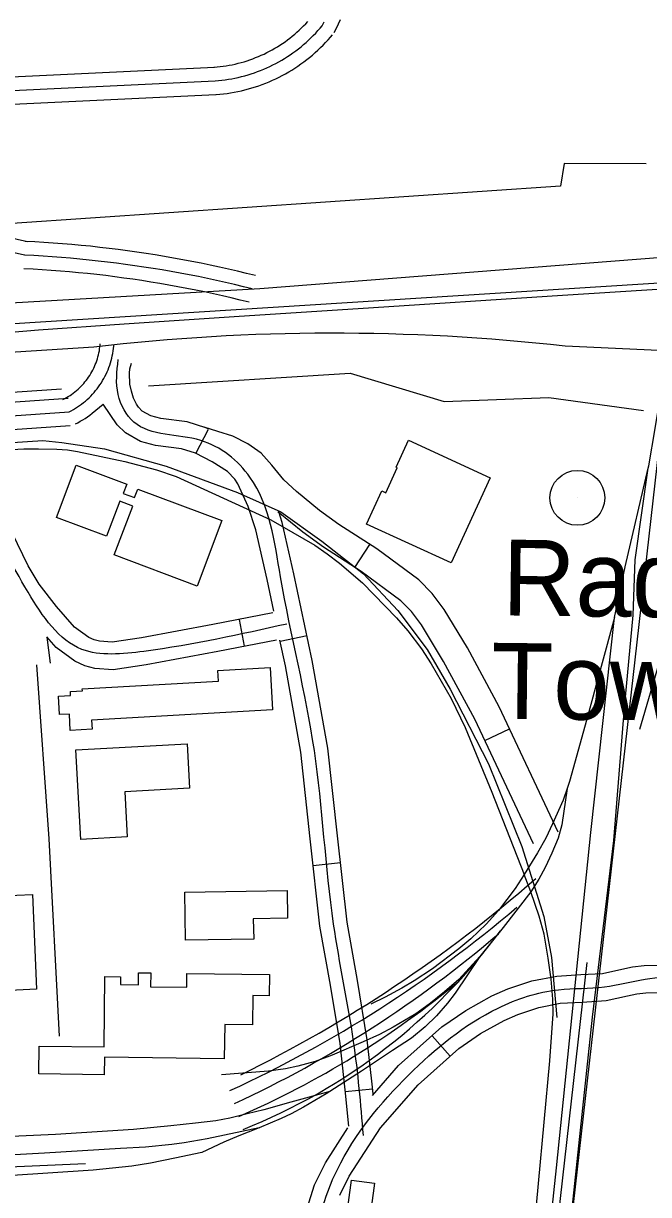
# Model space of a CAD drawing. Extents: x 3313442 to 3351311, y 721974 to 747360.
# Drawn here: x 3327167 to 3327852, y 729153 to 730435 of the extents above; entities that cross this region are included whole.
import ezdxf

# ---------------------------------------------------------------- set-up
doc = ezdxf.new("R2010")
doc.units = 0
for name, color, linetype in [('V-BLDG-OTLN', 7, 'Continuous'), ('V-RAIL-TRAK', 7, 'Continuous'), ('V-ROAD-CNTR', 7, 'Continuous'), ('V-TOPO-SHOR', 7, 'Continuous'), ('V-TOPO-TOWR', 7, 'Continuous'), ('V-TOPO-TOWR-IDEN', 7, 'Continuous')]:
    doc.layers.add(name, color=color, linetype=linetype)

msp = doc.modelspace()

# ---------------------------------------------------------------- linework, layer by layer
at = {"layer": 'V-BLDG-OTLN'}
for points in [[(3327588.8, 729979), (3327678.2, 729937.9), (3327635.5, 729844.9), (3327543, 729887.3), (3327559.6, 729923.5), (3327563.9, 729921.5), (3327576.5, 729948.9), (3327575.3, 729949.4)], [(3327203.4, 729894.6), (3327224.9, 729951.8), (3327280.4, 729930.9), (3327276.6, 729920.9), (3327289, 729916.2), (3327292.5, 729925.6), (3327384.5, 729891), (3327357.6, 729819.3), (3327266.7, 729853.5), (3327286.9, 729907), (3327272.7, 729912.4), (3327258.2, 729873.9)], [(3327241.9, 729672.7), (3327242.5, 729662.7), (3327218.6, 729661.4), (3327217.6, 729679.2), (3327206.7, 729678.6), (3327205.6, 729698.7), (3327219, 729699.5), (3327218.8, 729703.8), (3327231.8, 729704.5), (3327231.6, 729706.9), (3327380.8, 729715.3), (3327380.1, 729727), (3327437.4, 729730.3), (3327440, 729683.9)], [(3327230.1, 729542), (3327224.8, 729640.1), (3327346.7, 729646.7), (3327349.3, 729598), (3327278.3, 729594.1), (3327281, 729544.8)], [(3327344.1, 729484.3), (3327455.9, 729485.9), (3327456.4, 729455.6), (3327419, 729455.1), (3327419.4, 729432.8), (3327344.9, 729431.7)], [(3327177.1, 729481.7), (3327181.7, 729377.9), (3327130, 729375.6), (3327125.4, 729479.4)], [(3327255.6, 729314.7), (3327256.6, 729391.7), (3327273.7, 729391.5), (3327273.6, 729383.1), (3327293.1, 729382.8), (3327293.2, 729395.9), (3327306.8, 729395.7), (3327306.6, 729380.7), (3327346.1, 729380.1), (3327346.3, 729395.2), (3327436.6, 729394), (3327436.3, 729370.7), (3327418.6, 729371), (3327418.1, 729339), (3327387.7, 729339.4), (3327387.2, 729301.7), (3327255.9, 729303.5), (3327255.6, 729284.1), (3327184.2, 729285.1), (3327184.6, 729315.7)], [(3327514.8, 729081.9), (3327526.5, 729168.8), (3327551.6, 729165.4), (3327539.9, 729078.5)]]:
    msp.add_lwpolyline(points, close=True, dxfattribs=at)
at = {"layer": 'V-RAIL-TRAK'}
for points in [[(3327851.4, 729948.5), (3327852, 729951), (3327858.9, 729992), (3327884.5, 730146.1), (3327904.5, 730266.7), (3327916, 730340.5), (3327930.1, 730430.7), (3327952.4, 730568.9)], [(3327183.8, 730099.8), (3327277.7, 730106.6), (3327403.5, 730115), (3327533.8, 730123.3), (3327757.4, 730137.9), (3327884.5, 730146.1), (3327892.7, 730146.7), (3328018.3, 730155.8), (3328042.5, 730157.3), (3328057.1, 730158.3), (3328070.7, 730159.1), (3328086.4, 730159.6), (3328145.1, 730159.2), (3328193.8, 730158.7), (3328212.7, 730158.5), (3328228.8, 730157.8), (3328260.8, 730155.5), (3328288.9, 730153.2), (3328318.8, 730150), (3328375.5, 730142.9), (3328414.4, 730137.2), (3328463.7, 730128.5), (3328497.9, 730121.4)], [(3327014.9, 730087.4), (3327110.7, 730093.9), (3327183.8, 730099.8)], [(3327059.4, 729961.3), (3327127.5, 729967.6), (3327167.7, 729969.8), (3327183.7, 729969.7), (3327203.9, 729969.4)], [(3327203.9, 729969.4), (3327215.5, 729968.4), (3327226.4, 729966.7), (3327278.5, 729955.7), (3327313, 729946.7), (3327334.4, 729939.5), (3327438, 729892), (3327486.2, 729864), (3327499.8, 729854.8), (3327513.5, 729844.6), (3327538.4, 729822.8), (3327575.6, 729784.7), (3327588.1, 729770.4), (3327603.2, 729750.5), (3327613.7, 729734.4), (3327635.5, 729696.4), (3327650.9, 729664.5), (3327680.2, 729593.8), (3327715.7, 729503.6)], [(3327658.3, 728335.8), (3327679.9, 728538.1), (3327686.9, 728603.1), (3327698.6, 728695.6), (3327703.3, 728743.6), (3327716.3, 728857.1), (3327751, 729182.2), (3327788.4, 729549.5), (3327814.6, 729784.9), (3327826.2, 729840.6), (3327851.4, 729948.5)], [(3327725.1, 728725.6), (3327734.4, 728833.8), (3327748.4, 728955.9), (3327762.4, 729082.6), (3327790.5, 729347.4), (3327813.8, 729540.9), (3327825.5, 729686), (3327834.9, 729787.4), (3327837, 729848), (3327851.4, 729948.5)], [(3327814.6, 729784.9), (3327784, 729673.7), (3327765.3, 729605.5), (3327762.6, 729597.6)], [(3327762.6, 729597.6), (3327756.8, 729557.8), (3327752.8, 729543.2), (3327746, 729526.9), (3327738.6, 729511.2), (3327731.6, 729498.5), (3327722.7, 729484.5), (3327692.7, 729445.6), (3327667.1, 729413.7), (3327643.9, 729388.4), (3327628.3, 729375), (3327613.1, 729362.7), (3327597, 729351.1), (3327572, 729336.2), (3327557.3, 729328.5), (3327539.4, 729320.3), (3327505.4, 729305.7), (3327486.6, 729298.7), (3327467.7, 729293.6), (3327454.1, 729290.6), (3327435.7, 729288.3), (3327384, 729284.2)], [(3327762.6, 729597.6), (3327758.3, 729584.8), (3327746.7, 729558.9), (3327739.3, 729543.5), (3327730.1, 729527.2), (3327715.7, 729503.6), (3327705.6, 729488.1), (3327687.6, 729464.2), (3327674, 729449), (3327657.3, 729433.1), (3327643.9, 729422)], [(3327703.3, 728743.6), (3327706.3, 728858.9), (3327706.8, 728889.1), (3327707.5, 728915.7), (3327709.3, 728943.5), (3327714.9, 729003.8), (3327725.1, 729097.9), (3327743.5, 729299.5), (3327747.2, 729350.8), (3327747, 729367.2), (3327745.1, 729388.9), (3327741.9, 729411.8), (3327737.4, 729438.2), (3327731.8, 729458), (3327722.7, 729484.5), (3327715.7, 729503.6)], [(3327643.9, 729422), (3327615, 729400.4), (3327595.2, 729387.1), (3327581.7, 729379), (3327563.3, 729369.3), (3327547.5, 729361.6)], [(3327667.1, 729413.7), (3327640, 729373.5), (3327631.5, 729362.8), (3327619.7, 729348.9), (3327607.2, 729336.9), (3327592.3, 729324.5), (3327571.3, 729310.9), (3327537.4, 729288.2), (3327502.6, 729265.8)], [(3327502.6, 729265.8), (3327460, 729254.1), (3327430.5, 729245.8), (3327412.4, 729241.3), (3327393.3, 729236.8), (3327377.8, 729233.7), (3327355.7, 729231.2), (3327328.6, 729228.2), (3327287.8, 729224.5), (3327202.4, 729218.8), (3327121.8, 729215.3), (3326843.8, 729200.9), (3326713, 729190.5), (3326658.4, 729186.5), (3326461.7, 729173.4), (3326168.2, 729152.8), (3326073.1, 729146.5)], [(3327502.6, 729265.8), (3327498.6, 729263.2), (3327473.9, 729248.8), (3327460.3, 729241.5), (3327449.5, 729236.4), (3327425.4, 729226.2), (3327423.7, 729225.5), (3327403, 729217.4), (3327386.6, 729210.5), (3327362.5, 729199.2), (3327333, 729192.8), (3327306.6, 729187.4), (3327286.1, 729184.2), (3327243.5, 729179.7), (3327011.5, 729164.4), (3326950.7, 729160.3), (3326888.4, 729156.2)], [(3327426, 729226.3), (3327425.4, 729226.2), (3327368.4, 729214.1), (3327343.2, 729209.7), (3327329.7, 729208), (3327300.9, 729205.1), (3327273.4, 729203.4), (3327190.4, 729198.3), (3327104.8, 729193.6), (3326981.7, 729185.9), (3326856.7, 729179.1), (3326685.3, 729167.5), (3326571.1, 729159.8)]]:
    msp.add_lwpolyline(points, dxfattribs=at)
at = {"layer": 'V-ROAD-CNTR'}
for p, q in [((3327356.1, 729964.6), (3327369.8, 729991.3)), ((3327530.2, 729839.8), (3327546.4, 729865)), ((3327409.4, 729753.5), (3327403.7, 729782.9)), ((3327448.5, 729759), (3327477.8, 729765.2)), ((3327672.5, 729650.2), (3327699.6, 729663)), ((3327484.6, 729513.3), (3327514.5, 729516.6)), ((3327614.8, 729327), (3327634.7, 729304.6)), ((3327519.7, 729266.1), (3327549.6, 729269))]:
    msp.add_line(p, q, dxfattribs=at)
for points in [[(3327375.9, 730387.5), (3327379.4, 730387.8), (3327382.7, 730388.2), (3327386, 730388.6), (3327389.3, 730389.1), (3327392.6, 730389.7), (3327395.9, 730390.3), (3327399.2, 730391), (3327402.4, 730391.8), (3327405.6, 730392.7), (3327408.9, 730393.6), (3327412.1, 730394.6), (3327415.2, 730395.6), (3327418.4, 730396.8), (3327421.5, 730398), (3327424.6, 730399.3), (3327427.6, 730400.6), (3327430.7, 730402), (3327433.7, 730403.5), (3327436.7, 730405), (3327439.6, 730406.6), (3327442.5, 730408.3), (3327445.4, 730410), (3327448.2, 730411.8), (3327451, 730413.6), (3327453.7, 730415.5), (3327456.4, 730417.5), (3327459.1, 730419.5), (3327461.7, 730421.6), (3327464.3, 730423.7), (3327466.8, 730425.9), (3327469.3, 730428.2), (3327471.7, 730430.5), (3327474, 730432.8), (3327476.4, 730435.2), (3327478.6, 730437.7)], [(3327377.1, 730372.6), (3327380.8, 730372.9), (3327384.5, 730373.3), (3327388.1, 730373.7), (3327391.7, 730374.3), (3327395.3, 730374.9), (3327398.9, 730375.6), (3327402.5, 730376.4), (3327406.1, 730377.3), (3327409.6, 730378.2), (3327413.2, 730379.2), (3327416.7, 730380.3), (3327420.2, 730381.5), (3327423.6, 730382.7), (3327427, 730384), (3327430.4, 730385.4), (3327433.8, 730386.9), (3327437.1, 730388.4), (3327440.4, 730390.1), (3327443.7, 730391.7), (3327446.9, 730393.5), (3327450.1, 730395.3), (3327453.2, 730397.2), (3327456.3, 730399.2), (3327459.4, 730401.2), (3327462.4, 730403.3), (3327465.4, 730405.5), (3327468.3, 730407.7), (3327471.2, 730410), (3327474, 730412.3), (3327476.8, 730414.7), (3327479.5, 730417.2), (3327482.1, 730419.7), (3327484.7, 730422.3), (3327487.3, 730424.9), (3327489.8, 730427.6), (3327492.2, 730430.4), (3327494.2, 730432.8)], [(3327494.2, 730432.8), (3327496.6, 730437.2)], [(3327507.4, 730425.7), (3327509.9, 730430.2), (3327512.3, 730434.9), (3327514.6, 730439.6)], [(3327378.4, 730357.6), (3327382.2, 730358), (3327386.2, 730358.4), (3327390.2, 730358.9), (3327394.1, 730359.5), (3327398.1, 730360.2), (3327402, 730360.9), (3327405.9, 730361.8), (3327409.8, 730362.7), (3327413.6, 730363.7), (3327417.5, 730364.9), (3327421.3, 730366), (3327425.1, 730367.3), (3327428.8, 730368.7), (3327432.6, 730370.1), (3327436.3, 730371.6), (3327439.9, 730373.2), (3327443.6, 730374.9), (3327447.2, 730376.7), (3327450.7, 730378.5), (3327454.2, 730380.4), (3327457.7, 730382.4), (3327461.1, 730384.4), (3327464.5, 730386.6), (3327467.8, 730388.8), (3327471.1, 730391.1), (3327474.3, 730393.4), (3327477.5, 730395.8), (3327480.6, 730398.3), (3327483.7, 730400.9), (3327486.7, 730403.5), (3327489.7, 730406.2), (3327492.6, 730409), (3327495.4, 730411.8), (3327498.2, 730414.7), (3327500.9, 730417.6), (3327503.5, 730420.6), (3327505.7, 730423.1)], [(3326610.2, 730351), (3327376.4, 730387.6)], [(3326595.9, 730335.3), (3327377.1, 730372.6)], [(3326611.6, 730321.1), (3327377.9, 730357.6)], [(3327171.8, 730196.4), (3327160.5, 730199), (3327149.2, 730201.6), (3327137.8, 730204), (3327126.4, 730206.4), (3327115, 730208.7), (3327103.6, 730210.9), (3327092.2, 730213), (3327080.7, 730215.1), (3327069.2, 730217.1), (3327057.8, 730218.9), (3327046.3, 730220.8), (3327034.8, 730222.5), (3327023.3, 730224.2), (3327011.7, 730225.7), (3327000.2, 730227.2), (3326988.6, 730228.6), (3326977.1, 730230), (3326965.5, 730231.2), (3326963.4, 730231.4)], [(3327168.5, 730181.8), (3327157.2, 730184.4), (3327146, 730186.9), (3327134.7, 730189.3), (3327123.4, 730191.7), (3327112.1, 730194), (3327100.8, 730196.2), (3327089.5, 730198.3), (3327078.1, 730200.3), (3327066.8, 730202.3), (3327055.4, 730204.1), (3327044, 730205.9), (3327032.6, 730207.7), (3327021.2, 730209.3), (3327009.8, 730210.9), (3326998.3, 730212.3), (3326986.9, 730213.7), (3326975.4, 730215.1), (3326964, 730216.3), (3326961.9, 730216.5)], [(3327421.5, 730159.3), (3327411.7, 730161.8), (3327401.7, 730164.2), (3327391.8, 730166.4), (3327381.8, 730168.7), (3327371.8, 730170.8), (3327361.8, 730172.9), (3327351.8, 730174.8), (3327341.8, 730176.7), (3327331.7, 730178.6), (3327321.6, 730180.3), (3327311.6, 730182), (3327301.5, 730183.5), (3327291.4, 730185), (3327281.2, 730186.5), (3327271.1, 730187.8), (3327261, 730189.1), (3327250.8, 730190.3), (3327240.7, 730191.4), (3327230.5, 730192.4), (3327220.4, 730193.3), (3327210.2, 730194.2), (3327200, 730194.9), (3327189.8, 730195.6), (3327179.6, 730196.3), (3327169.4, 730196.8), (3327169.2, 730196.8)], [(3321910.8, 729798.5), (3325213, 730008.8), (3325897.5, 730057.1), (3327426.3, 730145.3), (3327871.2, 730180)], [(3327417.9, 730144.8), (3327408.1, 730147.2), (3327398.3, 730149.5), (3327388.5, 730151.8), (3327378.6, 730154), (3327368.7, 730156.1), (3327358.8, 730158.2), (3327348.9, 730160.1), (3327339, 730162), (3327329.1, 730163.8), (3327319.1, 730165.5), (3327309.2, 730167.2), (3327299.2, 730168.7), (3327289.2, 730170.2), (3327279.2, 730171.6), (3327269.2, 730172.9), (3327259.2, 730174.2), (3327249.2, 730175.3), (3327239.1, 730176.4), (3327229.1, 730177.4), (3327219, 730178.4), (3327209, 730179.2), (3327198.9, 730180), (3327188.8, 730180.7), (3327178.8, 730181.3), (3327168.7, 730181.8), (3327168.5, 730181.8)], [(3328093, 730163.1), (3327927, 730155.1), (3326543.4, 730067.8), (3321912.7, 729768.7)], [(3327414.3, 730130.2), (3327404.6, 730132.6), (3327394.9, 730134.9), (3327385.1, 730137.2), (3327375.4, 730139.4), (3327365.7, 730141.4), (3327355.9, 730143.5), (3327346.1, 730145.4), (3327336.3, 730147.2), (3327326.5, 730149), (3327316.6, 730150.7), (3327306.8, 730152.3), (3327296.9, 730153.9), (3327287.1, 730155.4), (3327277.2, 730156.7), (3327267.3, 730158.1), (3327257.4, 730159.3), (3327247.5, 730160.4), (3327237.6, 730161.5), (3327227.6, 730162.5), (3327217.7, 730163.4), (3327207.8, 730164.3), (3327197.8, 730165), (3327187.9, 730165.7), (3327177.9, 730166.3), (3327167.9, 730166.8), (3327167.7, 730166.8)], [(3327600, 727590.2), (3327669.7, 728258.8), (3327867.9, 730009.3), (3327888, 730123.2)], [(3327244.3, 730081), (3325899.8, 729995.3), (3321914.9, 729742.6)], [(3327210.4, 730023.5), (3327212.6, 730024.6), (3327214.5, 730025.7), (3327216.4, 730026.9), (3327218.3, 730028.1), (3327220.1, 730029.3), (3327221.9, 730030.6), (3327223.7, 730032), (3327225.4, 730033.4), (3327227.1, 730034.9), (3327228.7, 730036.4), (3327230.3, 730037.9), (3327231.8, 730039.6), (3327233.3, 730041.2), (3327234.7, 730042.9), (3327236.1, 730044.6), (3327237.4, 730046.4), (3327238.7, 730048.2), (3327239.9, 730050.1), (3327241.1, 730052), (3327242.2, 730053.9), (3327243.2, 730055.9), (3327244.2, 730057.9), (3327245.2, 730059.9), (3327246, 730061.9), (3327246.8, 730064), (3327247.6, 730066.1), (3327248.3, 730068.2), (3327248.9, 730070.3), (3327249.4, 730072.5), (3327249.9, 730074.7), (3327250.4, 730076.8), (3327250.7, 730079), (3327251, 730081.2), (3327251.2, 730083.5), (3327251.3, 730084.6)], [(3327217.3, 730010.2), (3327219.7, 730011.4), (3327222, 730012.7), (3327224.3, 730014.1), (3327226.6, 730015.6), (3327228.8, 730017.1), (3327230.9, 730018.6), (3327233, 730020.3), (3327235.1, 730022), (3327237.1, 730023.7), (3327239.1, 730025.5), (3327241, 730027.4), (3327242.8, 730029.4), (3327244.6, 730031.3), (3327246.3, 730033.4), (3327248, 730035.5), (3327249.6, 730037.6), (3327251.1, 730039.8), (3327252.6, 730042), (3327254, 730044.3), (3327255.3, 730046.6), (3327256.6, 730049), (3327257.8, 730051.4), (3327258.9, 730053.8), (3327259.9, 730056.3), (3327260.9, 730058.7), (3327261.8, 730061.3), (3327262.6, 730063.8), (3327263.4, 730066.4), (3327264, 730069), (3327264.6, 730071.6), (3327265.1, 730074.2), (3327265.6, 730076.8), (3327265.9, 730079.5), (3327266.2, 730082.1), (3327266.3, 730083.4)], [(3327862.5, 730077.5), (3327760.5, 730082)], [(3327369.5, 729991.5), (3327367.1, 729992.7), (3327346.7, 729999.3), (3327317.7, 730002.8), (3327306.7, 730005.7), (3327297.4, 730011), (3327293.4, 730015.1), (3327291.1, 730018.4), (3327287.9, 730025.2), (3327285.5, 730032.8), (3327283.9, 730040.4), (3327283.3, 730052.6), (3327283.9, 730057.4), (3327285.6, 730063.3)], [(3325730.2, 729922), (3327216.3, 730025.2)], [(3325731.2, 729907.1), (3327217.3, 730010.2)], [(3327224.2, 729996.9), (3327226.8, 729998.2), (3327229.5, 729999.8), (3327232.2, 730001.4), (3327234.8, 730003), (3327237.4, 730004.8), (3327239.9, 730006.6), (3327242.4, 730008.6), (3327254.6, 730018.6)], [(3327441.5, 729791.9), (3327434.2, 729826.4), (3327421.7, 729880.9), (3327413.3, 729906.6), (3327402.1, 729931.5), (3327398.9, 729936.5), (3327390.8, 729944.7), (3327373.9, 729955.5), (3327355.6, 729964.9), (3327340.2, 729969.8), (3327312, 729973.3), (3327295.3, 729977.6), (3327278.9, 729987), (3327270.1, 729995.9), (3327254.6, 730018.6)], [(3325732.2, 729892.1), (3327218.4, 729995.2)], [(3327752.9, 729549.9), (3327688.2, 729687.1), (3327653.5, 729751.6), (3327628.1, 729793.7), (3327614.9, 729811.4), (3327600.1, 729826.1), (3327554.1, 729860.1), (3327512.7, 729886.7), (3327491.5, 729902.1), (3327466.2, 729922.9), (3327452.4, 729935.8), (3327439.4, 729951.8), (3327427.6, 729964.8), (3327413.1, 729975.2), (3327396.7, 729983.4), (3327380.3, 729988.8), (3327365, 729993.2)], [(3326136.1, 729898.9), (3326610.3, 729940.6), (3326886.9, 729959), (3327188.7, 729978.6), (3327209.2, 729976.5), (3327256.1, 729969.6), (3327323.4, 729950.7), (3327401.6, 729921.9), (3327449, 729900.8), (3327494.1, 729868.6), (3327539.6, 729832.7), (3327577.1, 729792.7), (3327609.5, 729750), (3327634.4, 729706.5), (3327676.5, 729624.8), (3327713, 729534.2), (3327737, 729457.7), (3327745.6, 729412.8), (3327751.3, 729346.8)], [(3327725.8, 729537.1), (3327661.5, 729673.6), (3327627.4, 729736.7), (3327603.1, 729777), (3327592.2, 729791.7), (3327580.5, 729803.2), (3327537, 729835.4), (3327495.8, 729861.9), (3327473.1, 729878.3), (3327446.3, 729900.3), (3327446, 729900.7)], [(3327550.2, 729263), (3327549.4, 729270.8), (3327543.7, 729322.6), (3327533.1, 729387.5), (3327521.7, 729451.3), (3327511.2, 729546), (3327500.7, 729641.7), (3327483.6, 729737.7), (3327463.5, 729832.9), (3327450.6, 729888.9), (3327446.8, 729900.7)], [(3327440.3, 729790.1), (3327374.6, 729777.3), (3327296.7, 729762.7), (3327264.4, 729757.9), (3327250.4, 729758.9), (3327244.7, 729760.4), (3327239, 729763.1), (3327223.3, 729774.5), (3327203.4, 729797), (3327184.7, 729821.3), (3327172.4, 729841.6), (3327154.8, 729877.8)], [(3327444.5, 729760.3), (3327380.2, 729747.8), (3327301.7, 729733.1), (3327265.6, 729727.8), (3327245.4, 729729.1), (3327234.4, 729732.2), (3327223.7, 729737.1), (3327203, 729752.2), (3327192.9, 729763.7)], [(3327193, 729763.5), (3327196.6, 729734.8)], [(3327523.5, 729228), (3327519.6, 729267.6), (3327514, 729318.5), (3327503.5, 729382.4), (3327492, 729447), (3327481.4, 729542.7), (3327471, 729637.4), (3327454.2, 729732), (3327448.2, 729760.1)], [(3327181.7, 729733), (3327195, 729542.6), (3327206.5, 729326.7)], [(3327561.9, 727368.4), (3327654.8, 728260.4), (3327784.6, 729407.3)], [(3327549.4, 729261.6), (3327578.1, 729294.4), (3327625.5, 729336.6), (3327651.8, 729354.8), (3327680.2, 729370.6), (3327697.7, 729378.4), (3327723.9, 729387.1), (3327751.2, 729392.4), (3327777.4, 729393.9), (3327801.4, 729395.3), (3327822.4, 729399.9), (3327834.3, 729402.5), (3327847, 729403.9), (3327891.2, 729404.5), (3327934.8, 729404.8), (3327986.9, 729404.6), (3328009, 729404.9)], [(3327513.8, 729152.4), (3327524, 729173.1), (3327558.3, 729226.2), (3327599.4, 729273.3), (3327644.1, 729312.9), (3327667.7, 729329.3), (3327693.6, 729343.8), (3327708.5, 729350.4), (3327731.5, 729358), (3327754.9, 729362.5), (3327779.2, 729363.9), (3327805.5, 729365.5), (3327828.8, 729370.6), (3327839, 729372.9), (3327848.7, 729373.9), (3327891.5, 729374.5)], [(3327034.5, 728900.2), (3327049, 728903.5), (3327120.1, 728921.2), (3327234.4, 728936.2), (3327347.5, 728949.4), (3327421.2, 728965.3), (3327494, 728988.5), (3327498.2, 728990.1), (3327500.7, 728991.3), (3327501.4, 728991.8), (3327502.1, 728992.5), (3327501.3, 728991.2), (3327500.9, 728990), (3327501.4, 728994.8), (3327499.4, 729006.6), (3327491, 729028.8), (3327483.4, 729053.7), (3327478.2, 729086.5), (3327475.7, 729119.6), (3327477.8, 729138.2), (3327485.9, 729163.6), (3327497.9, 729187.9), (3327522.6, 729226.1)], [(3327235.1, 729186.8), (3326083.8, 729136.4)]]:
    msp.add_lwpolyline(points, dxfattribs=at)
for centre, radius, start, end in [((3327506.9, 727831.6), 2264.7, 83.5711, 96.6587), ((3326746.6, 730624.9), 1493.7, 296.1632, 311.083), ((3326819.1, 730511.8), 1371, 294.7671, 310.3997), ((3326871, 730389.3), 1253, 294.8863, 310.6548), ((3327167.9, 729826.3), 648, 291.726, 323.6093), ((3326994.4, 730172.9), 1019.9, 293.6221, 309.5839)]:
    msp.add_arc(centre, radius, start, end, dxfattribs=at)
for points in [[(3326478, 730210.3), (3326482.3, 730403.3), (3326476.6, 730549.4), (3326473.6, 730637.7), (3326464.1, 730712.2), (3326371, 730713.7), (3326297.7, 730698.2), (3326169.7, 730725.9), (3326116.4, 730727.9), (3325982.6, 730689.7), (3325835.8, 730656.6), (3325666.2, 730661.4), (3325490.2, 730637.8), (3325403.5, 730634.8), (3325340.7, 730586.2), (3325201.4, 730524), (3325133.4, 730524.8), (3325012.9, 730513.5), (3324963.1, 730471.3), (3324981.9, 730365.9), (3324989.8, 730188.1), (3325009.7, 730055.8), (3325043.4, 729962.4), (3324998, 729812.5), (3325023.3, 729696.3), (3325064.5, 729608.4), (3325131.4, 729516.6), (3325150.4, 729377.8), (3325146.9, 729245.6), (3325126.5, 729132.5), (3325181.3, 729069.9), (3325338.9, 729062.3), (3325343.6, 728961.1), (3325372.9, 728878.1), (3325434.6, 728797.9), (3325537.3, 728748.8), (3325622.4, 728705), (3325714.6, 728675.4), (3325802.7, 728663.4), (3325976.3, 728695.1), (3326194.3, 728726.3), (3326466.6, 728765.3), (3326625.1, 728782), (3326781.8, 728849.7), (3326900.2, 728862.4), (3326981.7, 728872.8), (3327122.9, 728906.4), (3327350, 728934.6), (3327499.1, 728974.3), (3327515.7, 728986.7), (3327498, 729057.1), (3327490.8, 729119.3), (3327511, 729180.5), (3327588.8, 729283.8), (3327686.9, 729357.2), (3327753, 729377.4), (3327803.4, 729380.4), (3327847.9, 729388.9), (3327934.8, 729389.8), (3328039.1, 729390.2), (3328120.6, 729395.3), (3328249.2, 729404), (3328319.7, 729407.1), (3328384.2, 729401.5), (3328424.6, 729387.3), (3328470.1, 729368.6), (3328549.3, 729327.5), (3328661.1, 729275.7), (3328877.6, 729175.3), (3328980.2, 729125.8), (3329049.2, 729101.2), (3329067.8, 729104.6), (3329089, 729118.4), (3329113.6, 729147), (3329153.5, 729227.4), (3329182.5, 729301.2), (3329201.6, 729378.5), (3329199.7, 729471.2), (3329192.7, 729551.5), (3329166.9, 729646.7), (3329121.8, 729727.5), (3329091.5, 729778.7), (3329016.2, 729835.7), (3328941.7, 729880.1), (3328875.4, 729924.2), (3328789.7, 729967.9), (3328700.8, 730000), (3328643.6, 730009.5), (3328577, 730014.3), (3328435.2, 729993.9), (3328289, 729968.5), (3328169.5, 729944.5), (3328087.8, 729917.2), (3328042.9, 729880.4), (3327999.5, 729814.5), (3327967.2, 729727.1), (3328009.4, 729621.1)], [(3327539.6, 729217.8), (3327528.8, 729320.6), (3327506.9, 729449.2), (3327485.8, 729639.5), (3327448.8, 729829.6), (3327415.3, 729938.7), (3327361.4, 729978.8), (3327288.2, 729999), (3327271, 730029), (3327271.1, 730067.3)], [(3327455.6, 729777.8), (3327299.2, 729747.9), (3327231.3, 729750.1), (3327172.3, 729812.8), (3327115.6, 729890.6), (3326929.2, 729884.7), (3326778.3, 729875.3), (3326677.8, 729882.4), (3326518.7, 729881.2), (3326341.8, 729822.3), (3326240.5, 729767.1), (3326176.8, 729746), (3326056.8, 729783.3), (3325905.3, 729813.9), (3325785, 729805), (3325688.9, 729803.5), (3325557.2, 729830), (3325427.6, 729840.6), (3325340.1, 729811.9), (3325272.6, 729777), (3325154.7, 729774.5), (3325034.2, 729757.1), (3325013.3, 729752.1)]]:
    msp.add_spline(points, degree=3, dxfattribs=at)
at = {"layer": 'V-TOPO-SHOR'}
msp.add_line((3327208.8, 730035), (3326811.5, 730008.9), dxfattribs=at)
for points in [[(3327849.1, 730281.7), (3327759.5, 730282), (3327755.4, 730257.1), (3327154.8, 730216.5)], [(3327304.4, 730038.5), (3327524.9, 730052.4), (3327627.9, 730021.5), (3327742.7, 730025.7), (3327846.3, 730011.8)], [(3327842.3, 729662.8), (3327877.1, 729782.2), (3327881.3, 729851.9), (3327930.7, 729893.8), (3327938.2, 729962.7), (3328038.6, 729972), (3328130.5, 730003.9), (3328483.6, 730047.2)]]:
    msp.add_lwpolyline(points, dxfattribs=at)
at = {"layer": 'V-TOPO-TOWR'}
msp.add_line((3327773.8, 729916), (3327773.8, 729916), dxfattribs=at)
msp.add_circle((3327773.8, 729916), 30, dxfattribs=at)

# ---------------------------------------------------------------- texts
at = {"layer": 'V-TOPO-TOWR-IDEN'}
for s, p in [('Radio', (3327691.3, 729787.3)), ('Tower', (3327679.2, 729674.3))]:
    msp.add_text(s, height=83, rotation=359.3568, dxfattribs=at).set_placement(p)

doc.saveas('drawing.dxf')
